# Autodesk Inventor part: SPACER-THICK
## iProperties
Created: 2007-08
Part Number: SPACER-THICK
Material: Delrin, Black
Document SubType Name: Modeling
Density: 1.425 g/cm^3
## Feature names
1. Base1
